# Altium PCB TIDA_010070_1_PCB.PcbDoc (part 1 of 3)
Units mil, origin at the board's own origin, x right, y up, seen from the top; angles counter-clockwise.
Board outline 3224 x 3643 mil, 4 copper layers (Top Layer, Ground, Power, Bottom Layer), stack 90.4 mil thick; 156 components, 57 nets, 333 pads, 411 vias.
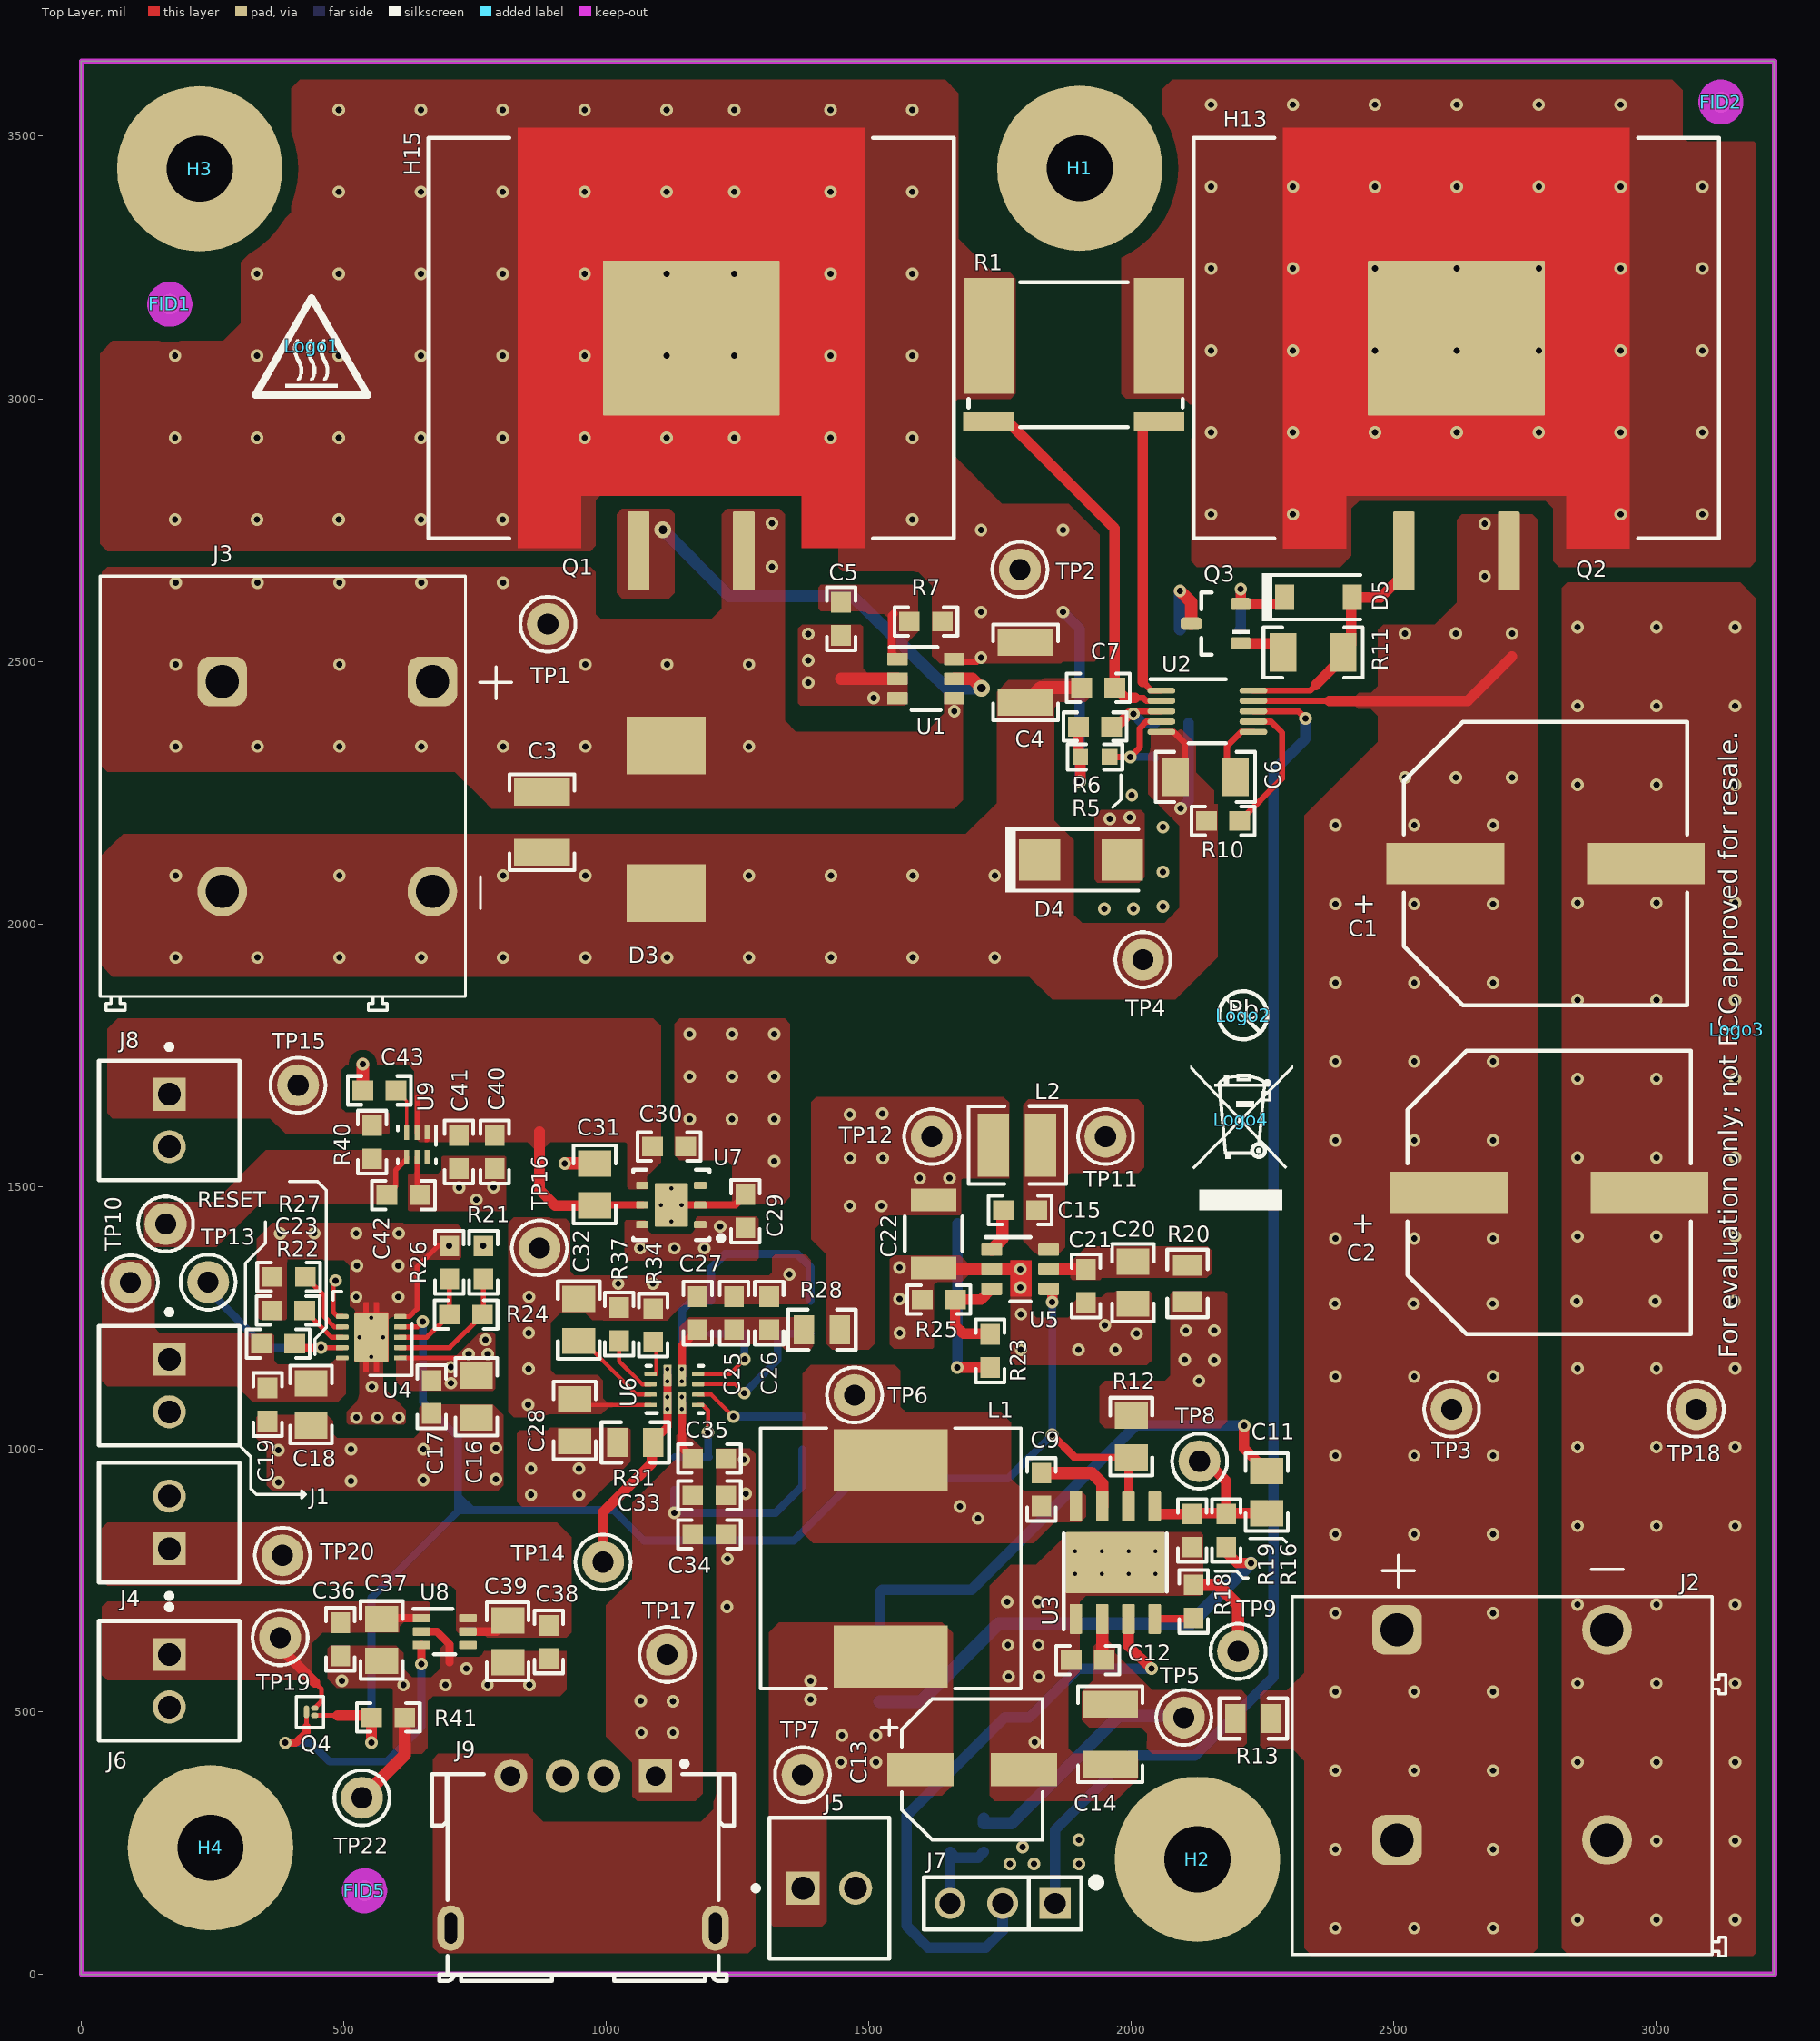
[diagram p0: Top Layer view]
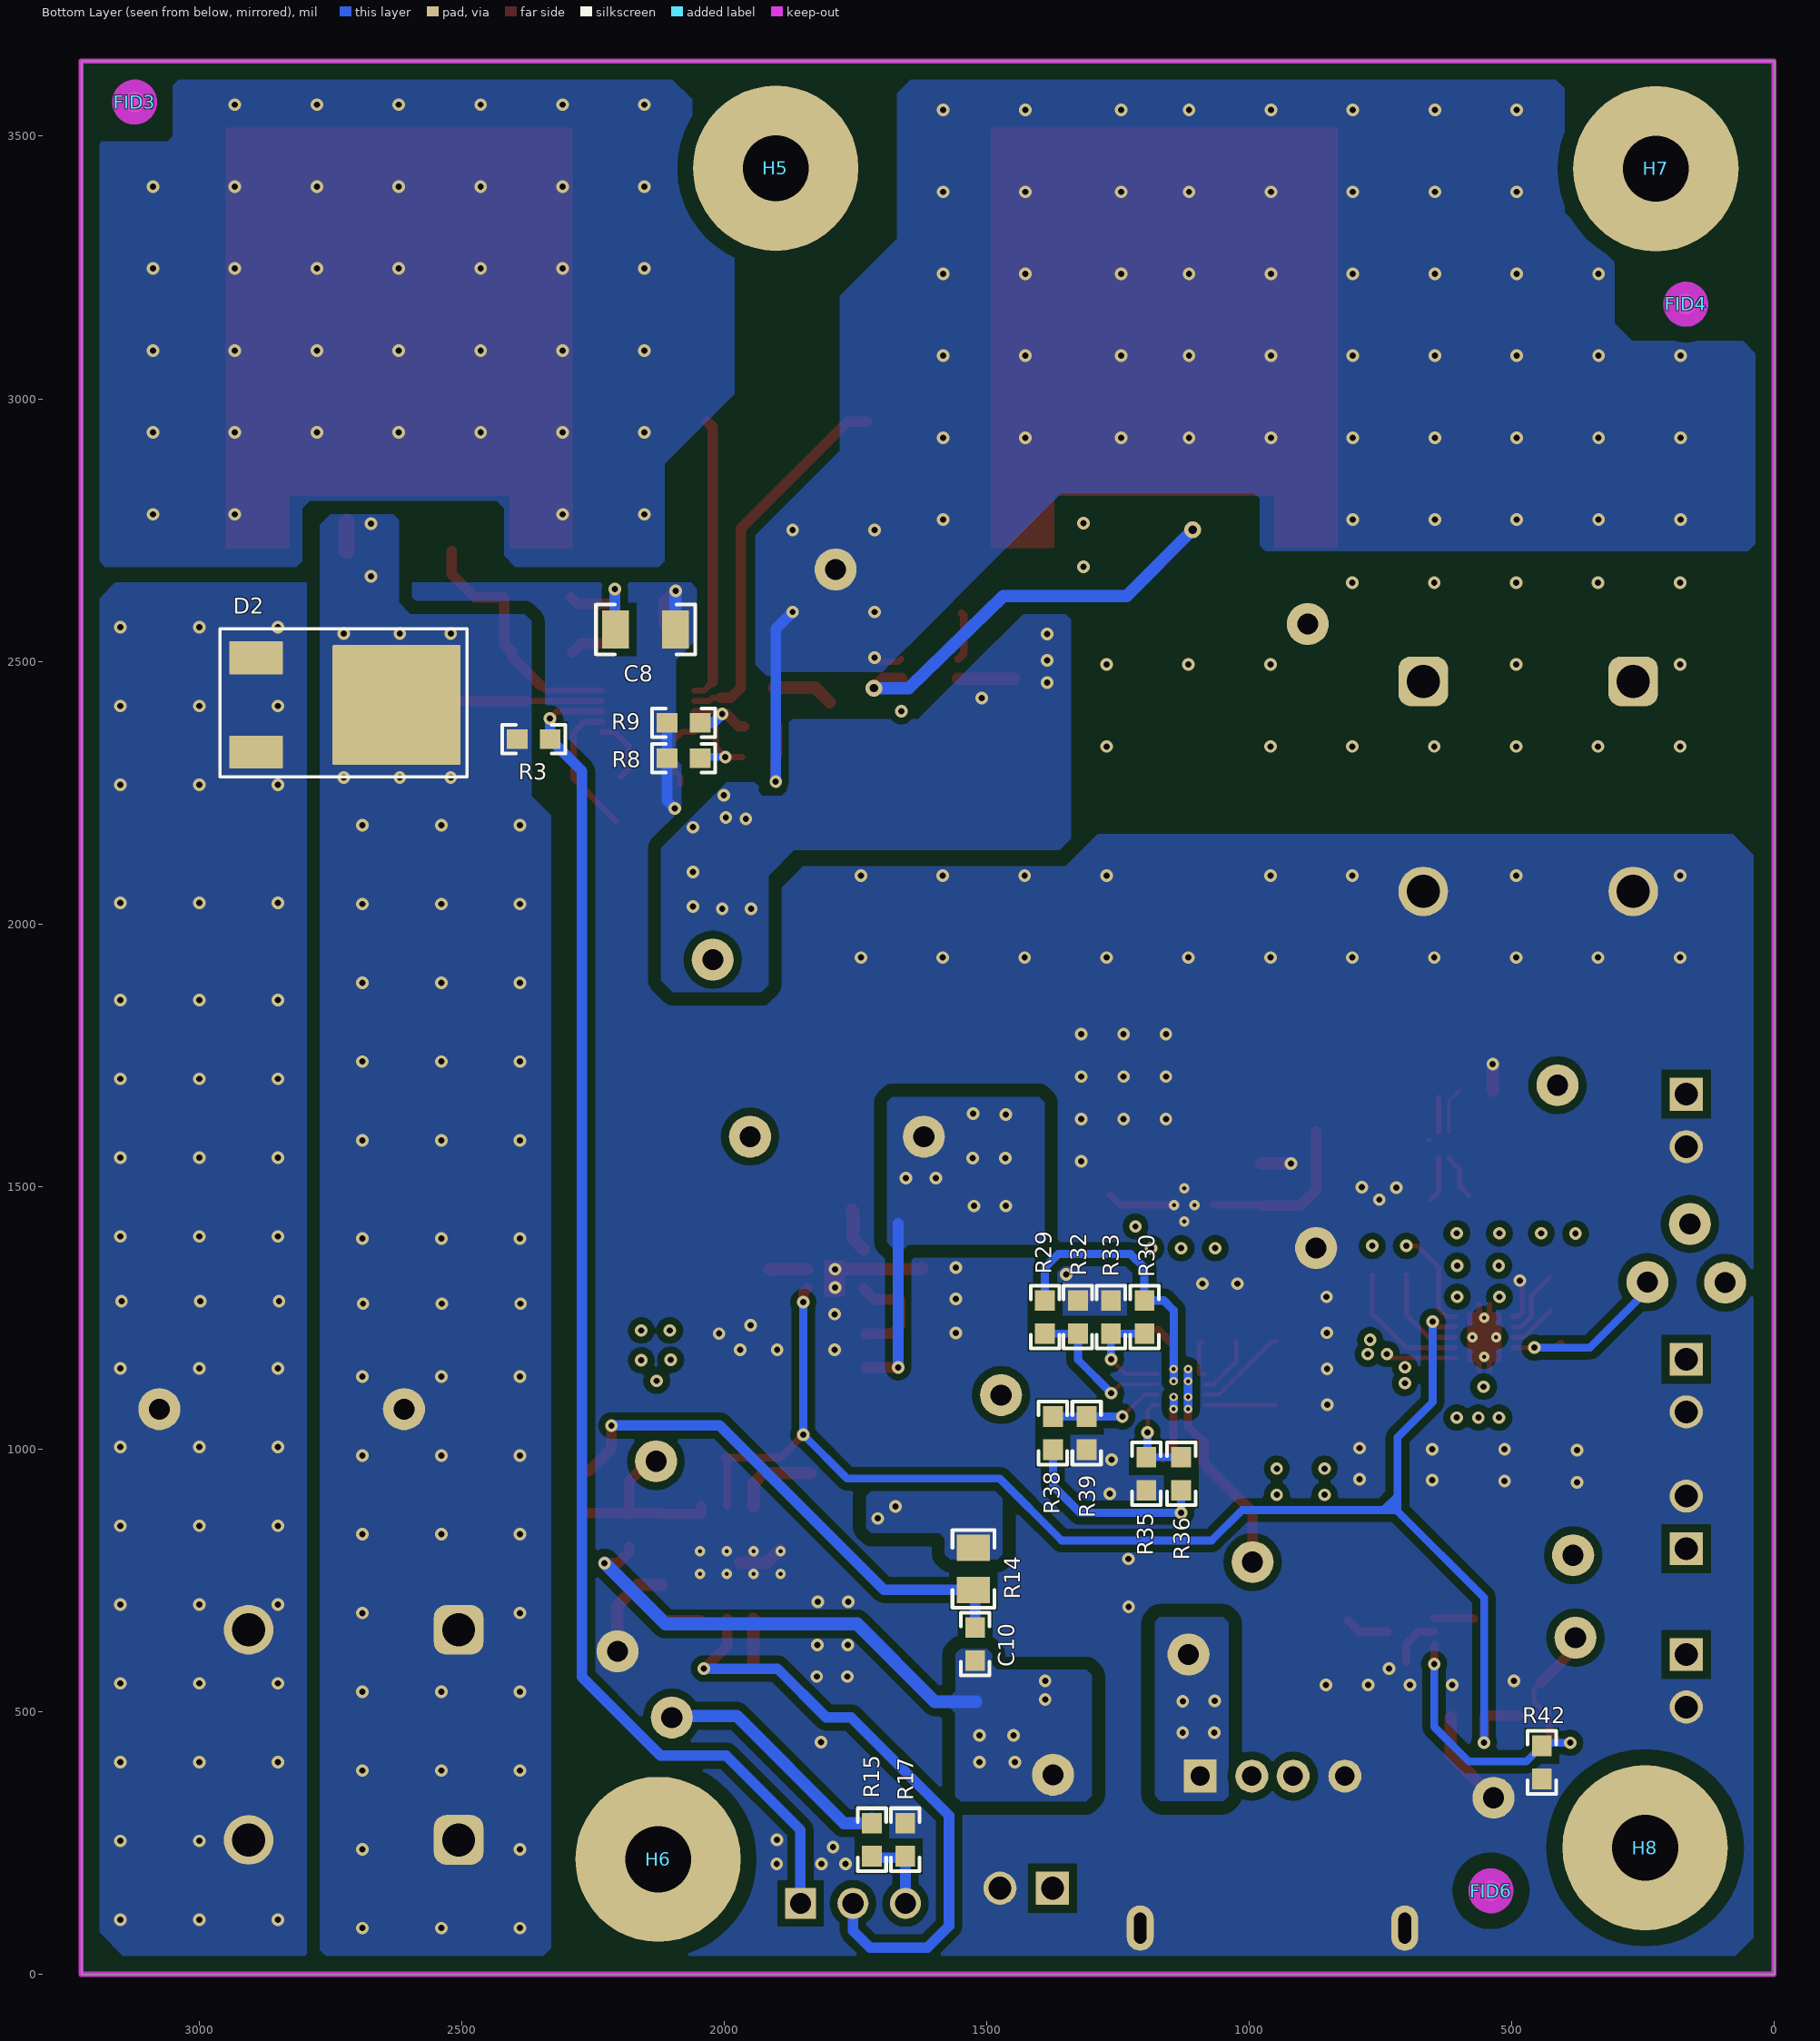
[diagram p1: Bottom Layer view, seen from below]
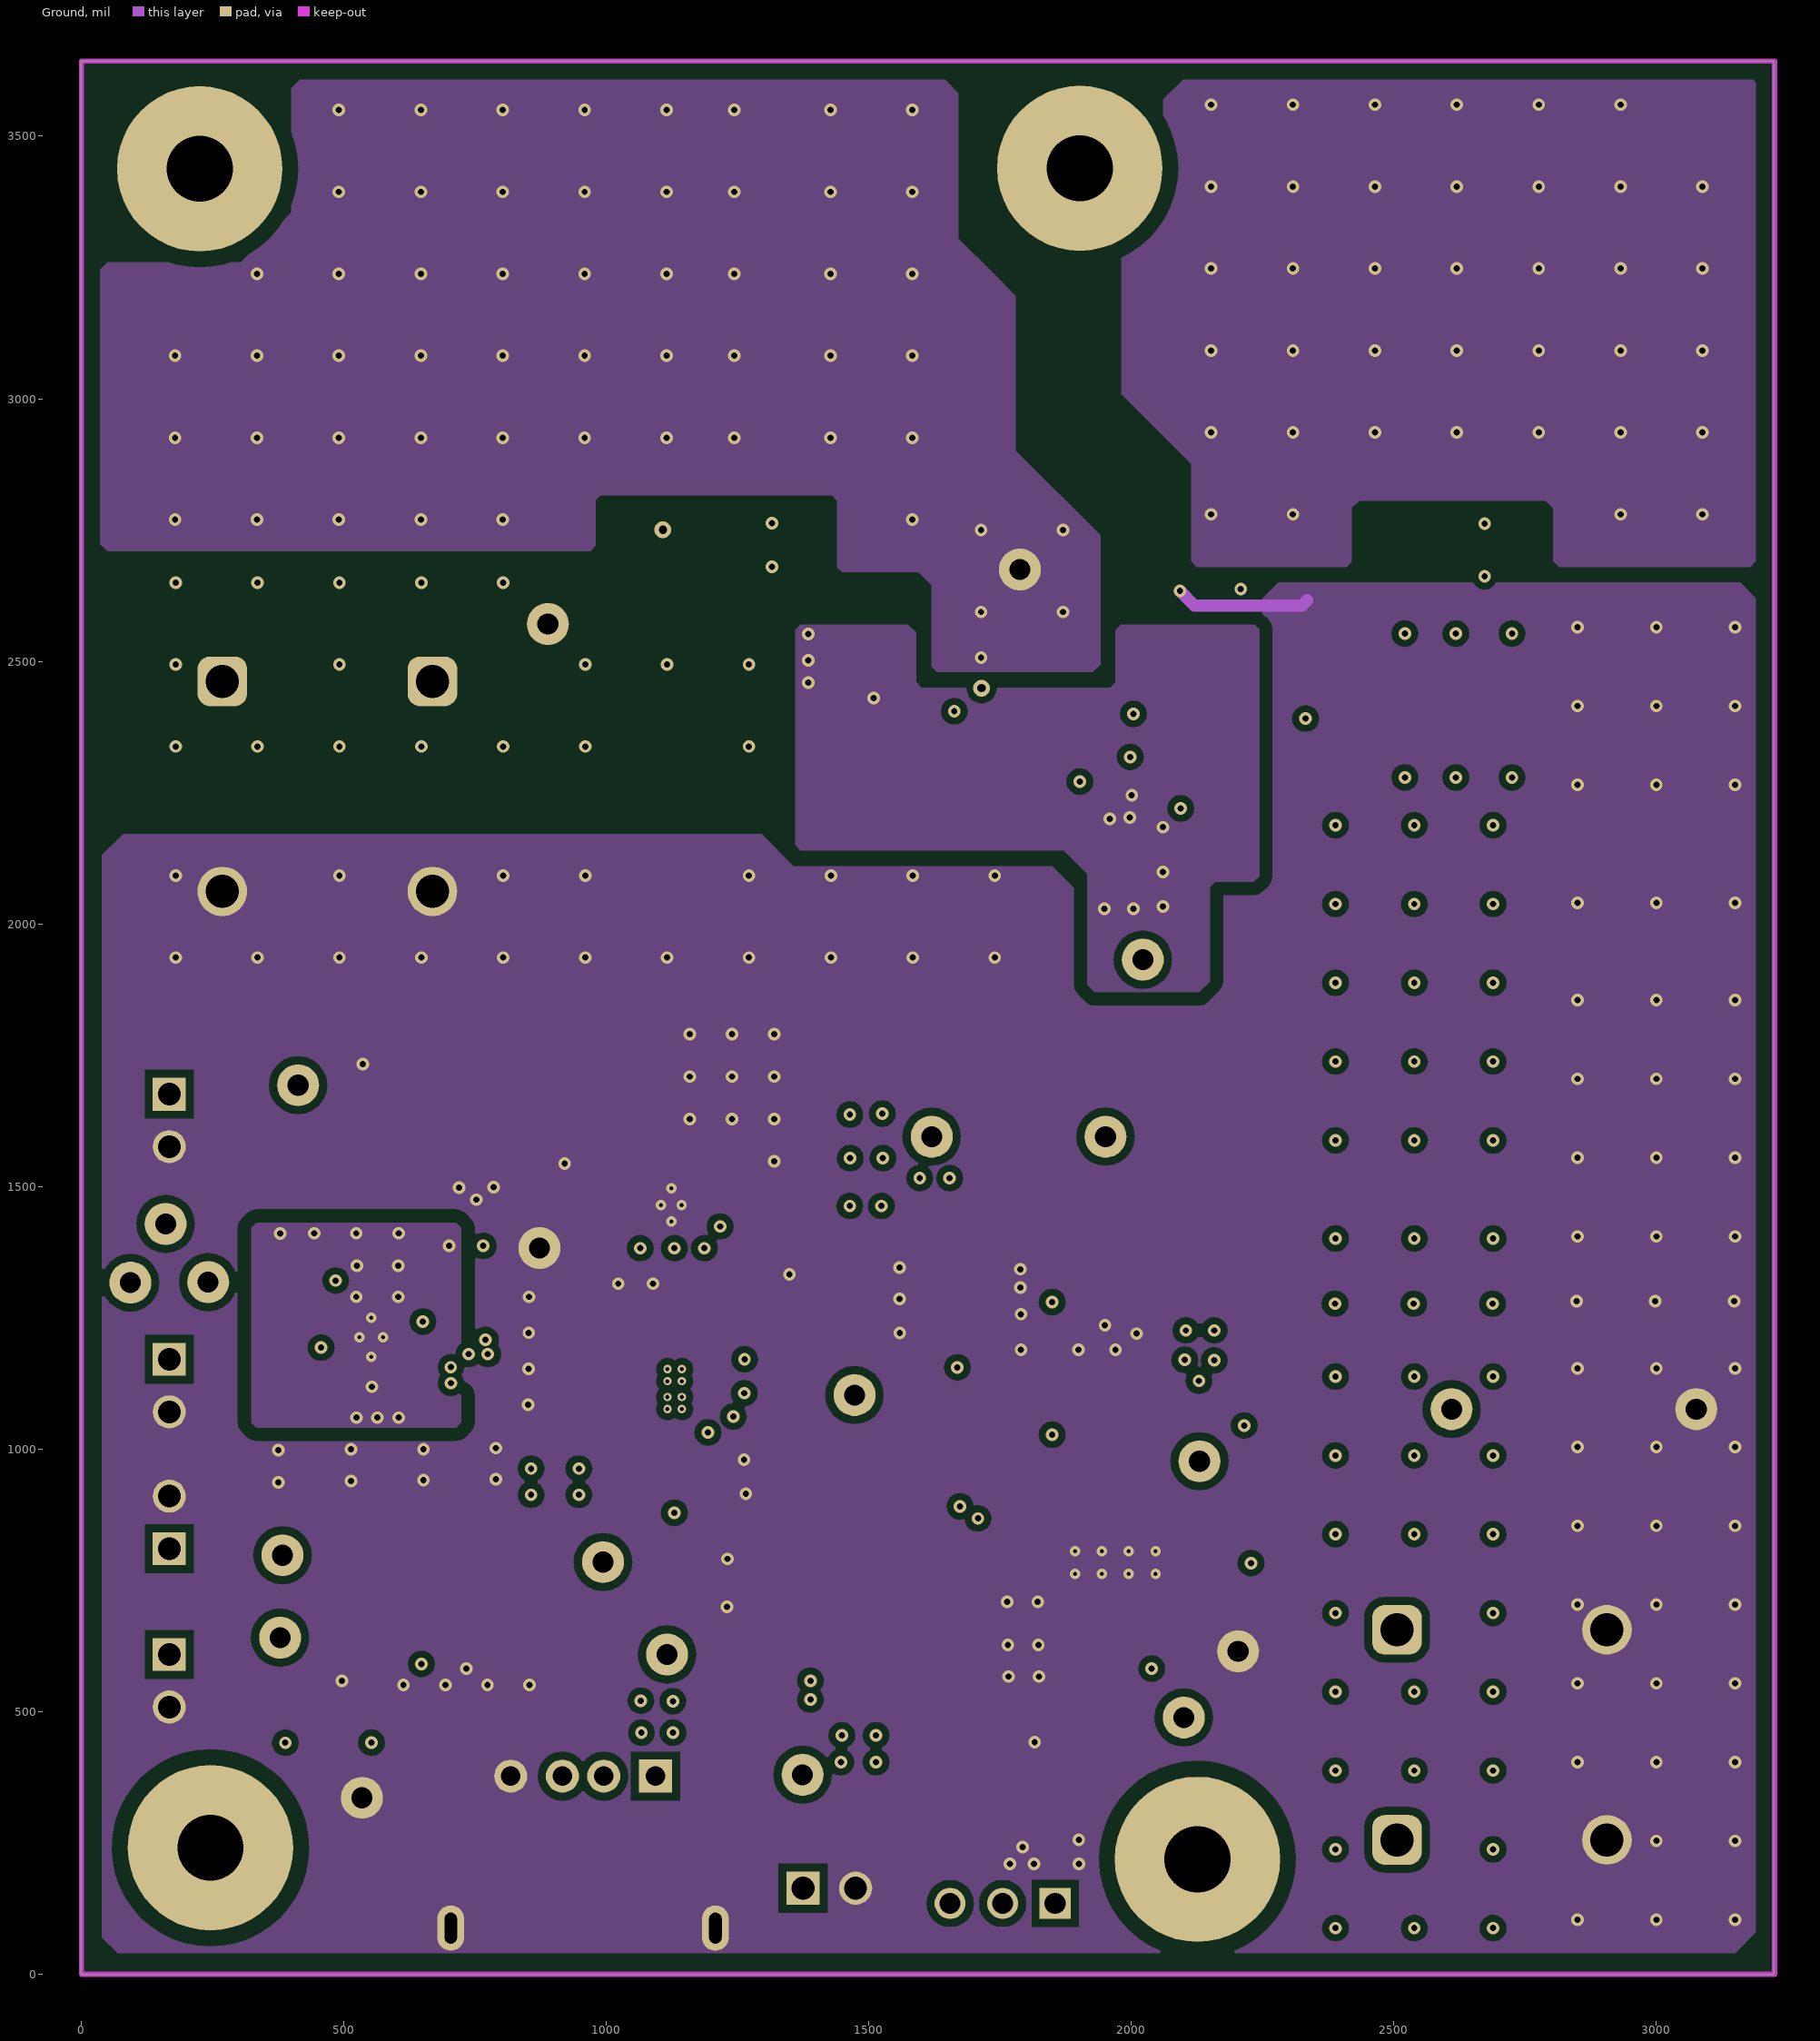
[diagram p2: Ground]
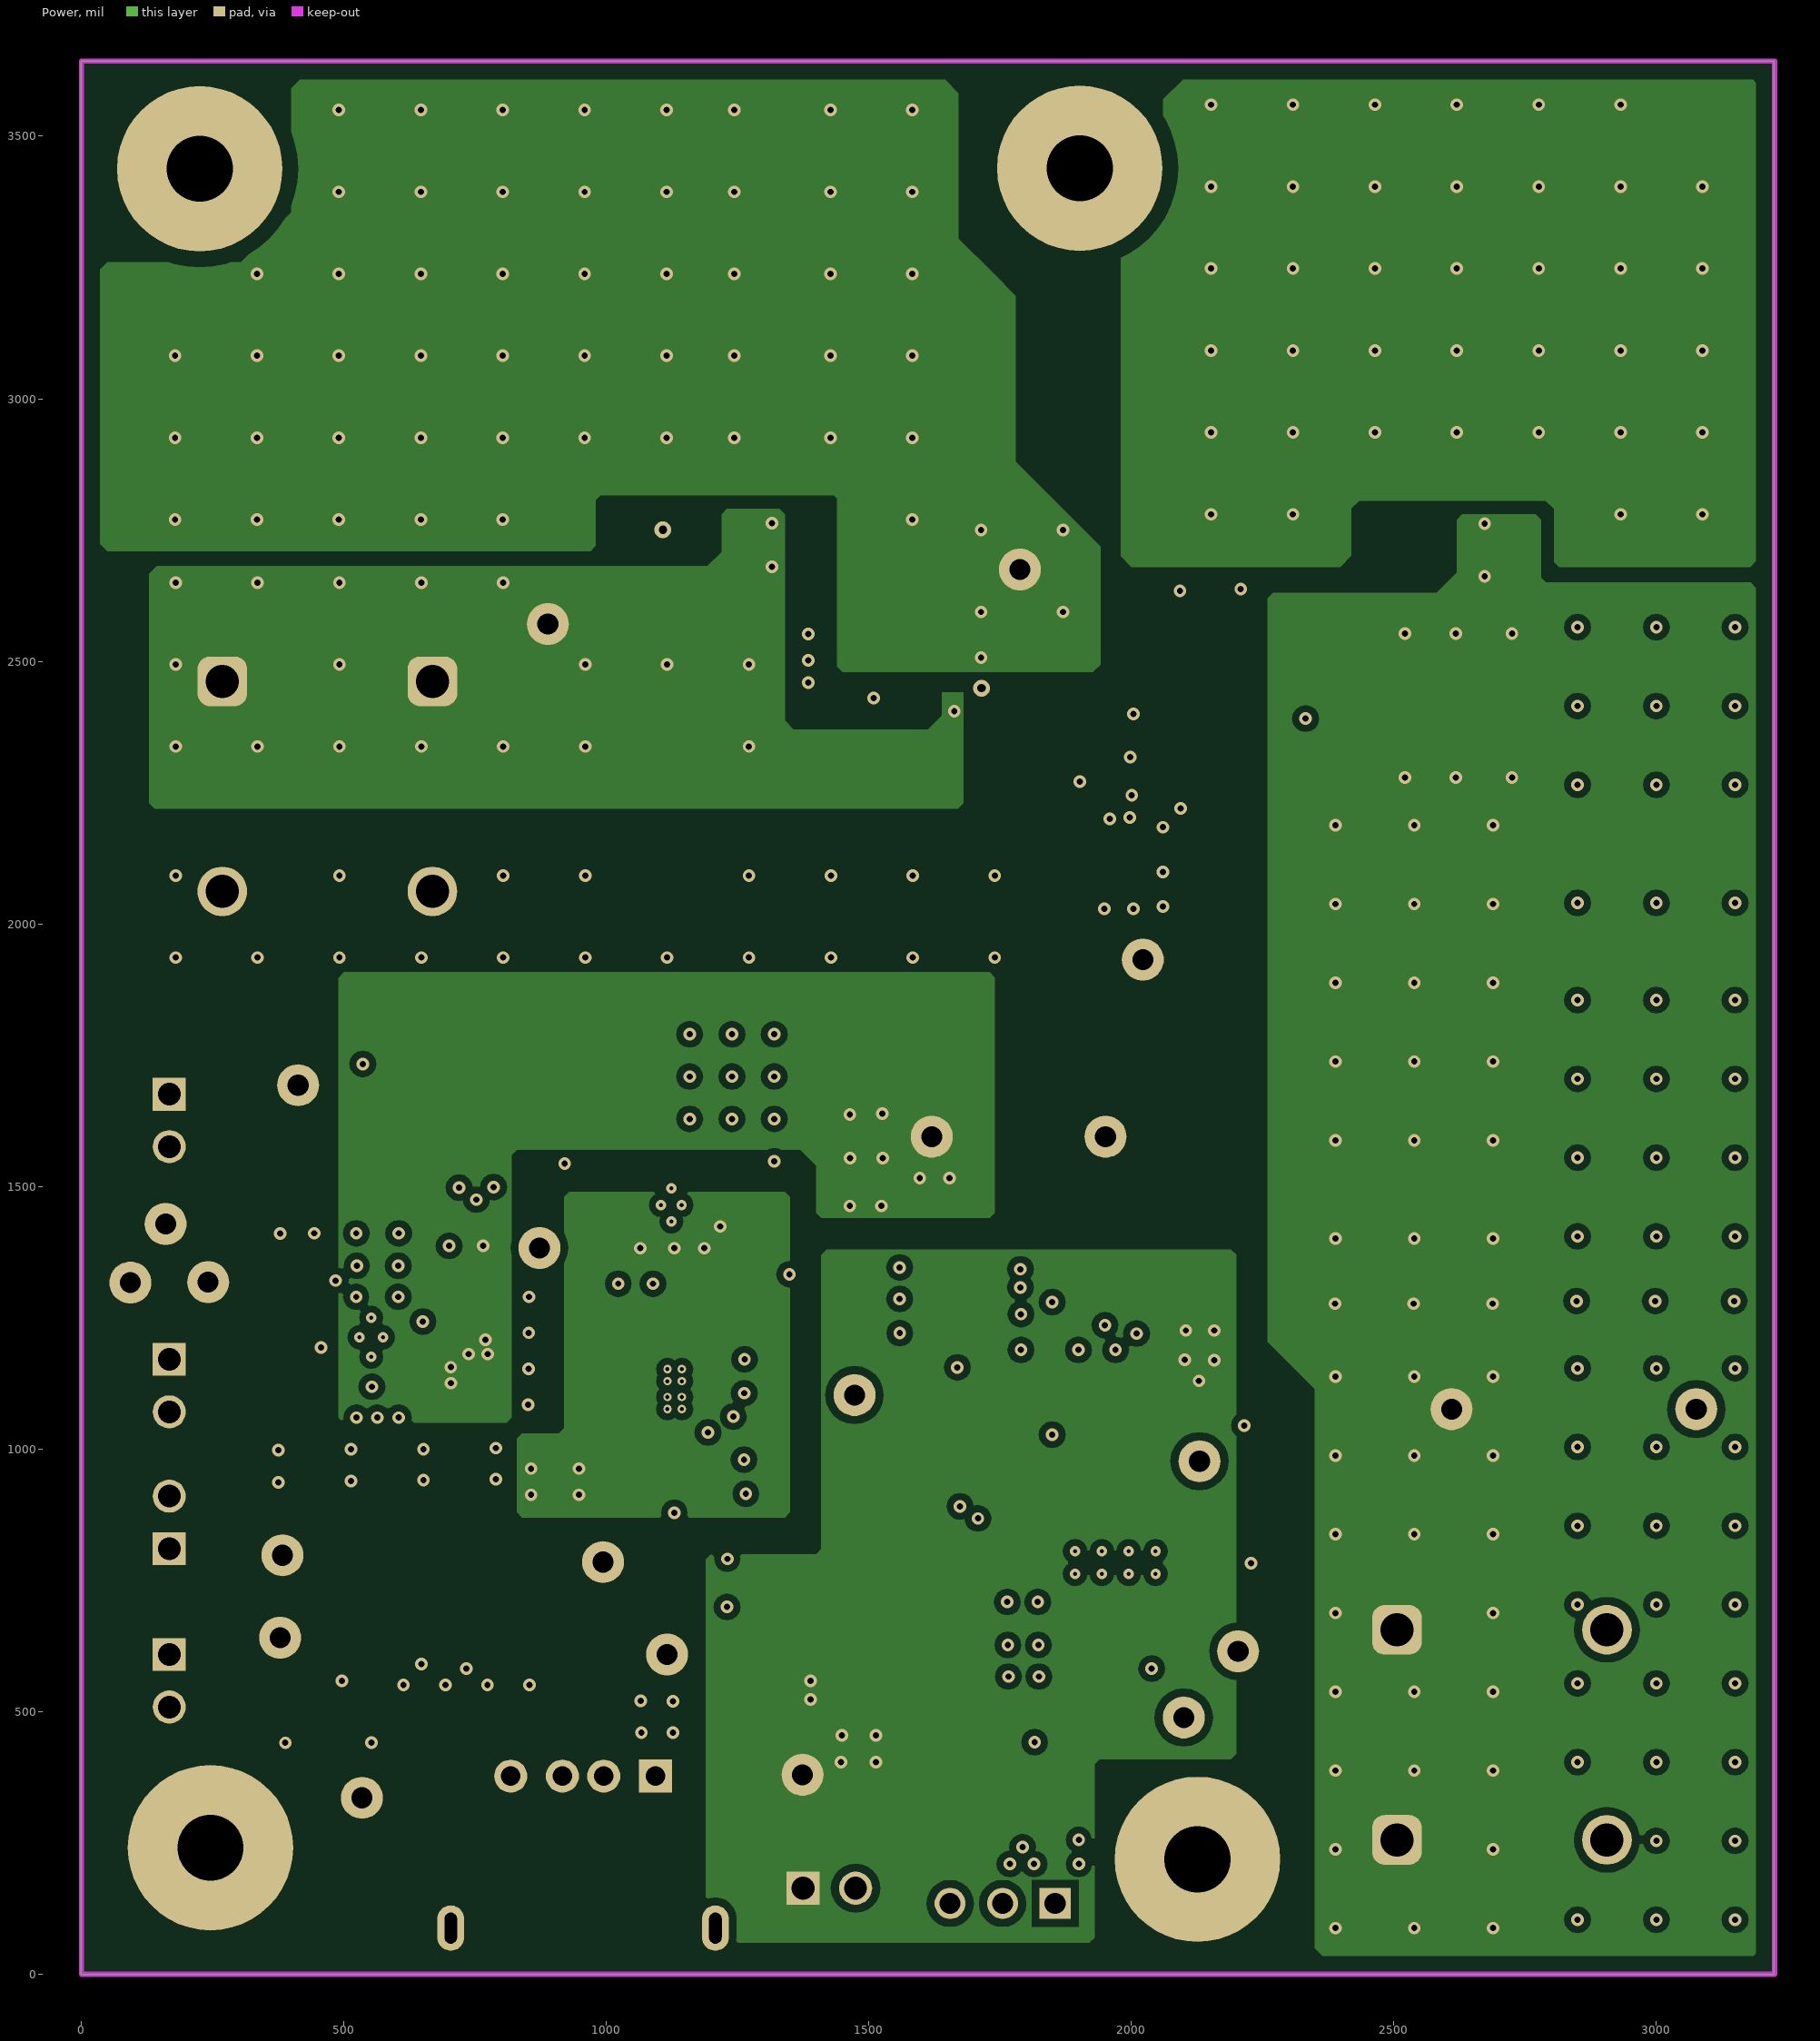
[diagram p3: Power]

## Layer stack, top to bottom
Top Solder: solder mask 0.4, Solder Resist, Dk 3.5
Top Layer: signal copper 2.8
Dielectric1: core 59.2, FR-4, Dk 4.8
Ground: signal copper 2.8
Dielectric 2: dielectric 10, Dk 4.2
Power: signal copper 2.8
Dielectric 3: dielectric 10, Dk 4.2
Bottom Layer: signal copper 2.8
Bottom Solder: solder mask 0.4, Solder Resist, Dk 3.5

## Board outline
0,0 3224,0 3224,3643 0,3643

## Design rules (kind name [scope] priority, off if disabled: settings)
AcuteAngle [All] p1: minimum=4.50000000000000E+0001 checktracksonly=FALSE
AssemblyTestPointUsage [All] p1: valid=2
BoardOutlineClearance BoardOutlineClearance_MountingHoles [OnCopper and InComponentClass('Mounting Holes')] p1: gap=39.37 ignorepadtopadclearanceinfootprint=FALSE
BoardOutlineClearance BoardOutlineClearance_Poly [OnCopper and IsPoly] p2: gap=25 ignorepadtopadclearanceinfootprint=FALSE
BoardOutlineClearance [OnCopper and Not InComponentClass('Logo') and not InComponentClass('FiducialMark') and not InRegion(1000,500,4000,800) and not InPoly] p3: gap=40 ignorepadtopadclearanceinfootprint=FALSE
Clearance room [WithinRoom('room Q4')] p1: gap=2 ignorepadtopadclearanceinfootprint=TRUE except(0: Arc-SMDPad Arc-Hole Track-Hole SMDPad-Hole THPad-Hole Via-Hole Fill-Hole Poly-Hole Region-Hole Text-Hole)
Clearance "MH PAD" [InPadClass('MH pad')] p2: gap=30 ignorepadtopadclearanceinfootprint=TRUE except(0: Arc-SMDPad Arc-THPad Arc-Hole Track-Hole SMDPad-Hole THPad-Hole Via-Hole Fill-Hole Poly-Hole Region-Hole Text-Hole)
Clearance Clearance_Keepouts [IsKeepOut] p3: gap=30 ignorepadtopadclearanceinfootprint=FALSE except(0: Arc-SMDPad Arc-THPad Arc-Hole Track-Hole SMDPad-Hole THPad-Hole Via-Hole Fill-Hole Poly-Hole Region-Hole Text-Hole)
Clearance Clearance_Poly [InPolygon] p4: gap=15 ignorepadtopadclearanceinfootprint=TRUE except(0: Arc-SMDPad Arc-Hole Track-Hole SMDPad-Hole THPad-Hole Via-Hole Fill-Hole Poly-Hole Region-Hole Text-Hole; 13: Via-Poly; 25: Poly-Poly)
Clearance [All] p5: gap=8 ignorepadtopadclearanceinfootprint=TRUE except(0: Arc-SMDPad Arc-THPad Arc-Hole Track-Hole SMDPad-Hole THPad-Hole Via-Hole Fill-Hole Poly-Hole Region-Hole Text-Hole; 7.8: Track-Track Track-SMDPad SMDPad-SMDPad SMDPad-THPad SMDPad-Via SMDPad-Fill SMDPad-Poly SMDPad-Region SMDPad-Text)
ComponentClearance "HEAT SINK" [InComponentClass('heat sink') vs InComponentClass('heat sink')] p1: gap=0 collisioncheckmode=3 verticalgap=0 showdistances=FALSE
ComponentClearance ComponentClearance_MountingHoles_FiducialMarks [InComponentClass('Mounting Holes') vs InComponentClass('FiducialMark')] p2: gap=50 collisioncheckmode=3 verticalgap=10 showdistances=FALSE
ComponentClearance ComponentClearance_Shunt [InComponentClass('Header') vs InComponentClass('Shunt')] p3: gap=0 collisioncheckmode=3 verticalgap=0 showdistances=FALSE
ComponentClearance ComponentClearance_Logo [InComponentClass('Logo')] p4: gap=50 collisioncheckmode=3 verticalgap=10 showdistances=FALSE
ComponentClearance ComponentClearance_ScrewToNut [(HasFootprint('NY PMS 440 0025 PH')) vs (HasFootprint('Keystone_1902C'))] p5: gap=5 collisioncheckmode=3 verticalgap=10 showdistances=FALSE
ComponentClearance ComponentClearance_MountingHoles [InComponentClass('Mounting Holes')] p6: gap=50 collisioncheckmode=3 verticalgap=100000 showdistances=FALSE
ComponentClearance ComponentClearance_SmallPassives [HasFootprint('0201*') or HasFootprint('0402*') or HasFootprint('0508') or HasFootprint('0603*') or HasFootprint('0612') or HasFootprint('0805*') or HasFootprint('0815*') or HasFootprint('0830*') or HasFootprint('1206*') or HasFootprint('1210*') or HasFootprint('1808*') or HasFootprint('1812*') or HasFootprint('1825*') or HasFootprint('2010*') or HasFootprint('2220*') or HasFootprint('2225*') or HasFootprint('2512*') or HasFootprint('2728*') or HasFootprint('3518*') vs HasFootprint('0201*') or HasFootprint('0402*') or HasFootprint('0508') or HasFootprint('0603*') or HasFootprint('0612') or HasFootprint('0805*') or HasFootprint('0815*') or HasFootprint('0830*') or HasFootprint('1206*') or HasFootprint('1210*') or HasFootprint('1808*') or HasFootprint('1812*') or HasFootprint('1825*') or HasFootprint('2010*') or HasFootprint('2220*') or HasFootprint('2225*') or HasFootprint('2512*') or HasFootprint('2728*') or HasFootprint('3518*')] p7: gap=14.96 collisioncheckmode=3 verticalgap=10 showdistances=FALSE
ComponentClearance ComponentClearance_THtoSMT [IsThruComponent vs IsSMTComponent] p8: gap=15 collisioncheckmode=3 verticalgap=30 showdistances=FALSE
ComponentClearance ComponentClearance_THtoTH [IsThruComponent vs IsThruComponent] p9: gap=30 collisioncheckmode=3 verticalgap=30 showdistances=FALSE
ComponentClearance [All] p10: gap=23 collisioncheckmode=3 verticalgap=10 showdistances=FALSE
DiffPairsRouting [All] p1: maxlimit=100 minlimit=10 mostfreqgap=10 toplayer_minwidth=15 toplayer_maxwidth=15 toplayer_prefwidth=15 midlayer1_minwidth=15 midlayer1_maxwidth=15 midlayer1_prefwidth=15 midlayer2_minwidth=15 midlayer2_maxwidth=15 midlayer2_prefwidth=15 bottomlayer_minwidth=15 bottomlayer_maxwidth=15 bottomlayer_prefwidth=15 maxuncoupledlength=1000
FabricationTestPointUsage TestPointUsage [All] p1: valid=2 allowmultiple=FALSE
FabricationTestpoint Testpoint [All] p1: side=3 testpointundercomponent=TRUE minsize=40 maxsize=100 preferedsize=60 minholesize=0 maxholesize=40 preferedholesize=32 testpointgrid=1 allowsidetop=TRUE allowsidebottom=TRUE usegrid=TRUE gridtolerance=0.01
FanoutControl Fanout_LCC [IsLCC] p1: bgadir=Out bgaviamode=Centered fanoutstyle=Auto fanoutdirection=Alternating viagrid=1 // Fanout_LCC (Default Rule)
FanoutControl Fanout_BGA [IsBGA] p2: bgadir=Out bgaviamode=Centered fanoutstyle=Auto fanoutdirection=Alternating viagrid=1 // Fanout_BGA (Default Rule)
FanoutControl Fanout_Default [All] p4: bgadir=Out bgaviamode=Centered fanoutstyle=Auto fanoutdirection=Alternating viagrid=1 // Fanout_Default (Default Rule)
FanoutControl Fanout_Small [(CompPinCount < 5)] p5: bgadir=Out bgaviamode=Centered fanoutstyle=Auto fanoutdirection=OutThenIn viagrid=1 // Fanout_Small (Default Rule)
HoleSize [All] p1: absolutevalues=TRUE maxlimit=251 minlimit=7.87 maxpercent=80.000 minpercent=20.000
MinimumAnnularRing MinimumAnnularRing_ThermalPadVias [IsVia and InAnyComponent] p1: minimumring=5.91
MinimumAnnularRing [All] p2: minimumring=4
MinimumSolderMaskSliver MinimumSolderMaskSliver_Logo [InComponentClass('Logo') vs InComponentClass('Logo')] p1: minsoldermaskwidth=0.7
MinimumSolderMaskSliver [All] p2: minsoldermaskwidth=3.94
PlaneConnect [All] p1: planeconnectstyle=Direct reliefexpansion=10 reliefentries=4 reliefconductorwidth=10 reliefairgap=10
PolygonConnect [All] p1: connectstyle=Direct reliefconductorwidth=10 reliefentries=4 polygonreliefangle="90 Angle" airgapwidth=10
RoomDefinition "room Q4" [All] p1: confinementstyle=ConfineOut formatcopy=TRUE lockcomponents=FALSE outline 420,520 480,520 480,470 420,470
RoutingVias ThermalPadVias [IsVia and InAnyComponent] p1: holewidth=7.87 width=19.68 viastyle="Through Hole" minholewidth=7.87 minwidth=19.68 maxholewidth=12.99 maxwidth=23.62
RoutingVias [All] p2: holewidth=12 width=24 viastyle="Through Hole" minholewidth=7 minwidth=16 maxholewidth=40 maxwidth=65
SilkToBoardRegionClearance [Not ((IsComment or IsDesignator) And (Hide <> 'False')) and not InRegion(1000,500,4000,800)] p1:
SilkToSilkClearance SilkToSilkClearance_Pb-FreeLogo [(HasFootprint('Pb-Free_Overlay_Medium') OR HasFootprint('Pb-Free_Overlay_Small')) vs (HasFootprint('Pb-Free_Overlay_Medium') OR HasFootprint('Pb-Free_Overlay_Small'))] p1: silktosilkclearance=0
SilkToSilkClearance [All] p2: silktosilkclearance=3.94
SilkToSolderMaskClearance SilkToComponentPadClearance [(IsPad or IsFill or IsRegion) and InAnycomponent] p1: minsilkscreentomaskgap=5 clearancetoexposedcopper=TRUE
SilkToSolderMaskClearance "Silk to Solder Mask Opening" [All] p2: minsilkscreentomaskgap=3.94 clearancetoexposedcopper=FALSE
SolderMaskExpansion [All] p1: expansion=1.97
UnRoutedNet [All] p1: checkbadconnections=TRUE
Width [All] p1: maxlimit=100 minlimit=6 preferedwidth=10 checkconnectedcopper=TRUE
14 further rules are at their usual default settings.

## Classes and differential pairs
component class TIDA_010070_Sheet2_09: C15 C16 C17 C18 C19 C20 C21 C22 C23 C25 C26 C27 C28 C29 C30 C31 C32 C33 C34 C35 C36 C37 C38 C39 C40 C41 C42 C43 L2 Q4 R20 R21 R22 R23 R24 R25 R26 R27 R28 R29 R30 R31 R32 R33 R34 R35 R36 R37 R38 R39 R40 R41 R42 RESET TP10 TP11 TP12 TP13 TP14 TP15 TP16 TP17 TP18 TP19 TP20 TP21 TP22 U4 U5 U6 U7 U8 U9
component class Header: J7
pad class "MH pad": H1-1 H2-1 H3-1 H4-1 H5-0 H6-0 H7-0 H8-0
component class TIDA_010070_Sheet1_09: C1 C2 C3 C4 C5 C6 C7 C8 C9 C10 C11 C12 C13 C14 D2 D3 D4 D5 H13 H15 J1 J2 J3 J4 J5 J6 J7 J8 J9 L1 Q1 Q2 Q3 R1 R3 R5 R6 R7 R8 R9 R10 R11 R12 R13 R14 R15 R16 R17 R18 R19 TP1 TP2 TP3 TP4 TP5 TP6 TP7 TP8 TP9 U1 U2 U3
component class AssemblyNote: ZZ1 ZZ2 ZZ3 ZZ4
component class FiducialMark: FID1 FID2 FID3 FID4 FID5 FID6
component class TIDA_010070_Hardware: FID1 FID2 FID3 FID4 FID5 FID6 H1 H2 H3 H4 H5 H6 H7 H8 Logo1 Logo2 Logo3 Logo4 ZZ1 ZZ2 ZZ3 ZZ4
component class "Mounting Holes": H1 H2 H3 H4
component class "heat sink": H13 H15 Q1 Q2

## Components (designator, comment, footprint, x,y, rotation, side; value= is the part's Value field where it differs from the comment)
C1 "EEV-EB2C330SQ" EB_H16 2789,2115 r0 top locked value=33uF
C2 "EEV-EB2C330SQ" EB_H16 2796,1489 r0 top locked value=33uF
C3 "CGA6N3X7R2A225K230AB" 1210_250 878,2194 r90 top value=2.2uF
C4 "CGA6N3X7R2A225K230AB" 1210_250 1799,2479 r90 top value=2.2uF
C5 "HMK107B7104KAHT" 0603 1447.23,2581 r270 top value=0.1uF
C6 "CC1206KRX7R9BB123" 1206 2141,2280.09 r0 top value=0.012uF
C7 "HMK107B7104KAHT" 0603 1937,2450 r180 top value=0.1uF
C8 "12065C103KAT2A" 1206 2149.86,2561 r0 bottom value=0.01uF
C9 "C0603C222K5RACTU" 0603 1829,923 r90 top value=2200pF
C10 "C0603C222K5RACTU" 0603 1522,628.84 r90 bottom value=2200pF
C11 "C0805C470J5GACTU" 0805_HV 2258,918.1 r90 top value=47pF
C12 "HMK107B7104KAHT" 0603 1917,597.8 r180 top value=0.1uF
C13 "EEE-FK1V470P" SM_RADIAL_D 1697,390 r0 top value=47uF
C14 "CGA6N3X7R2A225K230AB" 1210_250 1960,457 r90 top value=2.2uF
C15 "06033C104KAT2A" 0603 1788.46,1454.85 r0 top value=0.1uF
C16 "C2012X8R1C105K125AB" 0805_HV 752.64,1100 r90 top value=1uF
C17 "06033C104KAT2A" 0603 667.64,1099.5 r270 top value=0.1uF
C18 "GRM21BZ71E106KE15L" 0805_HV 438,1085.03 r90 top value=10uF
C19 "06033C104KAT2A" 0603 355,1085 r270 top value=0.1uF
C20 "C2012X7R1V475K125AC" 0805_HV 2003.19,1317 r90 top value=4.7uF
C21 "06033C104KAT2A" 0603 1913.46,1310.79 r90 top value=0.1uF
C22 "C3225X5R1C156M250AA" 1210_280 1623.46,1409.85 r90 top value=15uF
C23 "C0603C223K4RACTU" 0603 394.5,1264 r180 top value=0.022uF
C25 "06033C104KAT2A" 0603 1243.5,1259 r270 top value=0.1uF
C26 "06033C104KAT2A" 0603 1310.5,1259 r270 top value=0.1uF
C27 "06033C104KAT2A" 0603 1174.5,1259 r270 top value=0.1uF
C28 "C2012X7R1V475K125AC" 0805_HV 940,1055 r270 top value=4.7uF
C29 "06033C104KAT2A" 0603 1265,1452.91 r90 top value=0.1uF
C30 "06033C104KAT2A" 0603 1119.89,1576 r0 top value=0.1uF
C31 "C2012X8R1C105K125AB" 0805_HV 978,1504 r270 top value=1uF
C32 "C0805C105K5RACTU" 0805_HV 948,1246 r270 top value=1uF
C33 "06033C104KAT2A" 0603 1196.5,912 r180 top value=0.1uF
C34 "06033C104KAT2A" 0603 1196.5,837.45 r180 top value=0.1uF
C35 "06033C104KAT2A" 0603 1196.5,982 r180 top value=0.1uF
C36 "06033C104KAT2A" 0603 494,638 r270 top value=0.1uF
C37 "C2012X8R1C105K125AB" 0805_HV 572.33,636.58 r90 top value=1uF
C38 "06033C104KAT2A" 0603 891,633 r270 top value=0.1uF
C39 "C2012X8R1C105K125AB" 0805_HV 812.54,634 r90 top value=1uF
C40 "06033C104KAT2A" 0603 788,1565.8 r270 top value=0.1uF
C41 "GCM188R71C105KA64D" 0603 719.16,1565.8 r270 top value=1uF
C42 "06033C104KAT2A" 0603 614,1483.93 r0 top value=0.1uF
C43 "C0603C332K5RACTU" 0603 568,1683 r180 top value=3300pF
D2 "VS-6CWQ10FN-M3" DPAK 2758,2417 r180 bottom value=100V
D3 "5.0SMDJ75CA" SMC_Bi 1114.33,2199 r90 top value=75V
D4 "10MQ100NTRPBF" SMA 1903.93,2122 r0 top value=100V
D5 "1N4148W-7-F" SOD-123 2356.47,2622 r0 top value=100V
FID1 "Fiducial" Fiducial10-20 169,3180 r0 top
FID2 "Fiducial" Fiducial10-20 3123,3565 r0 top
FID3 "Fiducial" Fiducial10-20 3123,3565 r180 bottom
FID4 "Fiducial" Fiducial10-20 169,3180 r90 bottom
FID5 "Fiducial" Fiducial10-20 540,159 r90 top
FID6 "Fiducial" Fiducial10-20 540,159 r90 bottom
H1 "NY PMS 440 0025 PH" "NY PMS 440 0025 PH" 1902,3439 r0 top locked
H2 "NY PMS 440 0025 PH" "NY PMS 440 0025 PH" 2126,219 r0 top locked
H3 "NY PMS 440 0025 PH" "NY PMS 440 0025 PH" 226,3438 r0 top locked
H4 "NY PMS 440 0025 PH" "NY PMS 440 0025 PH" 246.37,241 r0 top locked
H5 "1902C" Keystone_1902C 1902.53,3439 r180 bottom locked
H6 "1902C" Keystone_1902C 2126,219 r180 bottom locked
H7 "1902C" Keystone_1902C 226,3438 r180 bottom locked
H8 "1902C" Keystone_1902C 246.37,241 r180 bottom locked
H13 "7109DG" Aavid_7109DG 2619,3115.49 r0 top locked
H15 "7109DG" Aavid_7109DG 1162,3115.62 r0 top
J1 "282834-2" TEC_282834-2 168,1121 r270 top
J2 "1986660-2" TE-1986660-2 2706,456 r0 top locked
J3 "1986660-2" TE-1986660-2 469,2262 r270 top locked
J4 "282834-2" TEC_282834-2 168,860.44 r90 top
J5 "282834-2" TEC_282834-2 1425,164 r0 top
J6 "282834-2" TEC_282834-2 168,559 r270 top
J7 "PEC03SAAN" CONN_PEC03SAAN 1755,135 r180 top locked
J8 "282834-2" TEC_282834-2 168,1626 r270 top
J9 "614 104 150 121" WURTH_614104150121 956.03,377.37 r0 top
L1 "MSS1210-154KE" MSS1210 1542,792 r270 top locked value=150uH
L2 "ME3220-682MLB" ME3220 1782.19,1579 r180 top locked value=6.8uH
Logo1 "CAUTION HOT SURFACE" IEC_HotSurface_Small 439,3100 r0 top (schematic designator LOGO1)
Logo2 "Pb-Free Symbol" Pb-Free_Overlay_Small 2213,1826 r0 top
Logo3 "FCC disclaimer" FCC_disclaimer 3153,1799 r90 top
Logo4 "WEEE logo" WEEE_Minimum 2208.52,1627 r0 top
Q1 "CSD19536KTT" KTT0002A 1162,2981.76 r90 top locked value=100V
Q2 "CSD19536KTT" KTT0002A 2619,2981.64 r90 top locked value=100V
Q3 "MMBT5401LT1G" SOT-23 2161.28,2572 r180 top value="150 V"
Q4 "CSD25501F3" YJN0003A 438.11,499.89 r180 top value=-20V
R1 "WSL40262L000FEB" WSL4026_310 1891,3084 r180 top locked value=0.002
R3 "CRCW0603102KFKEA" 0603 2363,2351.75 r180 bottom value=102k
R5 "CRCW060395K3FKEA" 0603_HV 1930.93,2318 r180 top value=95.3k
R6 "RT0603BRD0795K3L" 0603 1930.93,2375.75 r180 top value=95.3k
R7 "CRCW0603100RFKEA" 0603 1609,2576 r180 top value=100
R8 "CRCW06034K12FKEA" 0603 2077.52,2315.52 r0 bottom value=4.12k
R9 "RG1608P-7151-B-T5" 0603 2077.5,2383 r0 bottom value=7.15k
R10 "RG1608P-303-B-T5" 0603 2175,2196 r0 top value=30.0k
R11 "RC1206FR-071K02L" 1206 2346.38,2517 r180 top value=1.02k
R12 "CRCW080525K5FKEA" 0805_HV 2000,1024 r90 top value=25.5k
R13 "5106" 5106 2233,487 r180 top value=0
R14 "ERJ-6ENF4223V" 0805_HV 1525.53,772 r270 bottom value=422k
R15 "CRCW0603113KFKEA" 0603 1719,256.25 r270 bottom value=113k
R16 "RC0603FR-07576KL" 0603 2181,845 r90 top value=576k
R17 "CRCW060320K0FKEA" 0603 1655.32,256.25 r90 bottom value=20.0k
R18 "CRCW0603187KFKEA" 0603 2119,710 r90 top value=187k
R19 "RC0603FR-0749K9L" 0603 2116,845 r270 top value=49.9k
R20 "5106" 5106 2107.19,1315 r90 top value=0
R21 "CRCW060324K9FKEA" 0603 766,1355.5 r270 top value=24.9k
R22 "CRCW060349K9FKEA" 0603 375.21,1201 r0 top value=49.9k
R23 "CRCW060388K7FKEA" 0603 1731,1187 r90 top value=88.7k
R24 "CRCW06031K40FKEA" 0603 733,1256 r180 top value=1.40k
R25 "CRCW060322K1FKEA" 0603 1633.46,1284.85 r180 top value=22.1k
R26 "CRCW06038K06FKEA" 0603 701,1355.5 r90 top value=8.06k
R27 "CRCW060326K7FKEA" 0603 395.5,1328 r180 top value=26.7k
R28 "5106" 5106 1411.5,1227 r180 top value=0
R29 "CRCW060323K7FKEA" 0603 1389.5,1251.5 r270 bottom value=23.7k
R30 "CRCW060323K2FKEA" 0603 1200,1251.5 r270 bottom value=23.2k
R31 "5106" 5106 1055.8,1013 r180 top value=0
R32 "CRCW06034K99FKEA" 0603 1326.5,1251.5 r90 bottom value=4.99k
R33 "CRCW060313K3FKEA" 0603 1264,1251.5 r90 bottom value=13.3k
R34 "CRCW06030000Z0EA" 0603 1089.8,1236 r90 top value=0
R35 "CRCW06036K98FKEA" 0603 1196,953.05 r270 bottom value=6.98k
R36 "CRCW060314K3FKEA" 0603 1130,953.05 r270 bottom value=14.3k
R37 "CRCW060351K1FKEA" 0603 1025,1238 r90 top value=51.1k
R38 "CRCW060323K7FKEA" 0603 1374,1030.5 r90 bottom value=23.7k
R39 "CRCW06034K99FKEA" 0603 1310,1030.5 r270 bottom value=4.99k
R40 "CRCW060310K0FKEA" 0603 554.25,1584.5 r90 top value=10.0k
R41 "CRCW060312K7FKEA" 0603 585.12,489 r0 top value=12.7k
R42 "CRCW060310K2FKEA" 0603 442.82,403.71 r270 bottom value=10.2k
RESET "5000" Keystone5000 161,1428.75 r180 top
TP1 "5000" Keystone5000 889,2571 r0 top
TP2 "5000" Keystone5000 1788,2675 r90 top
TP3 "5000" Keystone5000 2610,1076.19 r90 top locked
TP4 "5001" Keystone5001 2022,1932 r90 top
TP5 "5000" Keystone5000 2100,489 r0 top
TP6 "5000" Keystone5000 1473,1103 r270 top
TP7 "5000" Keystone5000 1374,380 r0 top
TP8 "5000" Keystone5000 2130,977 r0 top
TP9 "5001" Keystone5001 2203.45,615 r0 top
TP10 "5000" Keystone5000 94,1317 r90 top
TP11 "5000" Keystone5000 1951,1595 r0 top
TP12 "5000" Keystone5000 1620,1595 r270 top
TP13 "5000" Keystone5000 242,1318 r90 top
TP14 "5000" Keystone5000 994,785 r0 top
TP15 "5000" Keystone5000 413.25,1693 r90 top
TP16 "5001" Keystone5001 873,1383 r90 top
TP17 "5000" Keystone5000 1116,609 r0 top
TP18 "5001" Keystone5001 3076,1076.19 r90 top locked
TP19 "5000" Keystone5000 379,641 r0 top
TP20 "5000" Keystone5000 383.54,798 r270 top
TP22 "5001" Keystone5001 535,336 r90 top
U1 "LM5050MK-1/NOPB" DDC0006A_N 1609,2466.94 r0 top
U2 "LM5069MM-2/NOPB" DGS0010A_N 2145,2405 r0 top
U3 "LM5164DDAT" DDA0008E_N 1969.62,784 r90 top locked
U4 "TPS26625DRCR" DRC0010J 552.64,1213 r180 top locked
U5 "TPS560430YDBVR" DBV0006A_N 1788.46,1342.62 r0 top locked
U6 "TPS2121RUXR" RUX0012A 1129.73,1113.57 r90 top locked
U7 "LP38691SD-3.3/NOPB" NGG0006A_V 1124,1464.91 r180 top locked
U8 "TPS22919DCKR" DCK0006A_N 692.33,652.58 r0 top locked
U9 "TPS3703A4330DSERQ1" DSE0006A 639.69,1579.15 r270 top locked
ZZ1 "This Assembly Note is for PCB labels only" AssemblyNoteLabel 1340.73,-1351 r0 top
ZZ2 "These assemblies are ESD sensitive, ESD precautions shall be observed." AssemblyNote 1340.73,-1448.22 r0 top
ZZ3 "These assemblies must be clean and free from flux and all contaminants. Use of no clean flux is not acceptable." AssemblyNote 1340.73,-1536.78 r0 top
ZZ4 "These assemblies must comply with workmanship standards IPC-A-610 Class 2, unless otherwise specified." AssemblyNote 1340.73,-1625.34 r0 top

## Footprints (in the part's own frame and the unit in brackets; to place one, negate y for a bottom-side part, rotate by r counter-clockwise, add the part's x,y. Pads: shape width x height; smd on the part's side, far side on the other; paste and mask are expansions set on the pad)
0603 [mm] "0603 from SM-752 data"
  rect 1x0.95 smd: 1(-0.8,0) 2(0.8,0)
  silkscreen extent -1.52,-0.69 1.52,0.69, body extent -0.87,-0.47 0.87,0.47, height 1
0603_HV [mil] "Ernesto recommended land pattern.  26 mil between pads."
  rect 30x30 smd: 1(-28,0) 2(28,0)
  silkscreen extent -52,-24 52,24, body extent -34,-19 34,19, height 39
0805_HV [mil] "0805 with 30mil clearance between pads"
  rect 50x63 smd: 1(-40,0) 2(40,0)
  silkscreen extent -74,-40 74,40, body extent -43,-29 43,29, height 57
1206 [mm] "1206 from SM-752 data"
  rect 1.3x1.85 smd: 1(-1.45,0) 2(1.45,0)
  silkscreen extent -2.4,-1.21 2.4,1.21, body extent -1.7,-0.9 1.7,0.9, height 1.35
1210_250 [mm] "1210"
  rect 1.3x2.7 smd: 1(-1.45,0) 2(1.45,0)
  silkscreen extent -2.32,-1.57 2.32,1.57, body extent -1.7,-1.35 1.7,1.35, height 2.5
1210_280 [mm] "SMD, 2-Leads, Body 3.6x2.8mm, Height 2.8mm"
  rect 1.1x2.2 smd: 1(-1.65,0) 2(1.65,0)
  silkscreen extent -0.84,-1.4 0.84,1.4, body extent -1.8,-1.4 1.8,1.4, height 2.8
5106 [mm] "Keystone"
  rect 0.99x1.4 smd: 1(-0.85,0) 2(0.88,0)
  silkscreen extent -1.63,-0.97 1.65,0.97, body extent -1.06,-0.69 1.06,0.69, height 0.84
Aavid_7109DG [mm] "Surface mount heat sink for D2PAK"
  rect 5x5 smd: 1(0,0)
  Top Layer region: -8.38,-10.16 -8.38,10.16 8.38,10.16 8.38,-10.16 5.335,-10.16 5.335,-7.62 -5.335,-7.62 -5.335,-10.16
  silkscreen extent -12.7,-9.69 12.7,9.69, body extent -12.7,-9.69 12.7,9.69, height 12.03
AssemblyNote [mil] "Assembly Note"
AssemblyNoteLabel [mil] "Assembly Note for PCB Labels"
CONN_PEC03SAAN [mm] "SULLINS"
  rect 1.5x1.5 hole 1.016: 1(-2.54,0)
  round 1.5 hole 1.016: 2(0,0) 3(2.54,0)
  silkscreen extent -4.72,-1.27 3.81,1.27, body extent -3.84,-1.3 3.84,1.3, height 8.38
DBV0006A_N [mm] "SOT23, 6-Leads, Body 2.9x1.6mm, Pitch 0.95mm, Lead Span 2.8mm, IPC Medium Density"
  rrect17% 1x0.6 smd: 1(-1.375,0.95) 2(-1.375,0) 3(-1.375,-0.95) 4(1.375,-0.95) 5(1.375,0) 6(1.375,0.95)
  silkscreen extent -1.68,-1.55 0.5,1.55, body extent -1.42,-1.46 1.42,1.46, height 1.12
DCK0006A_N [mm] "SOT23, 6-Leads, Body 2x1.3mm, Pitch 0.65mm, Lead Span 2.1mm, IPC Medium Density"
  rrect25% 0.85x0.4 smd: 1(-1.125,0.65) 2(-1.125,0) 3(-1.125,-0.65) 4(1.125,-0.65) 5(1.125,0) 6(1.125,0.65)
  silkscreen extent -1.5,-1.09 0.51,1.09, body extent -1.14,-1 1.14,1, height 0.95
DDA0008E_N [mm]
  rrect17% 1.45x0.6 smd: 1(-2.725,1.905) 2(-2.725,0.635) 3(-2.725,-0.635) 4(-2.725,-1.905) 5(2.725,-1.905) 6(2.725,-0.635) 7(2.725,0.635) 8(2.725,1.905)
  rrect7% 2.95x4.9 smd paste-1.5 mask-1.5: 9(0,0)
  rrect4% 2.4x3.1 on Top Paste: 9(0,0)
  rrect4% 2.4x3.1 on Top Solder: 9(0,0)
  silkscreen extent -3.22,-2.5 1.4,2.5, body extent -3,-2.45 3,2.45, height 1.57
DDC0006A_N [mm]
  rrect17% 1x0.6 smd: 1(-1.375,0.95) 2(-1.375,0) 3(-1.375,-0.95) 4(1.375,-0.95) 5(1.375,0) 6(1.375,0.95)
  silkscreen extent -1.75,-1.52 0.7,1.53, body extent -1.43,-1.48 1.43,1.49, height 0.92
DGS0010A_N [mm] "TSSOP, 10-Leads, Body 3x3mm, Pitch 0.5mm, IPC Medium Density"
  oval 1.35x0.3 smd: 1(-2.225,1) 2(-2.225,0.5) 3(-2.225,0) 4(-2.225,-0.5) 5(-2.225,-1) 6(2.225,-1) 7(2.225,-0.5) 8(2.225,0) 9(2.225,0.5) 10(2.225,1)
  silkscreen extent -2.75,-1.55 0.9,1.55, body extent -2.45,-1.5 2.45,1.5, height 0.96
DPAK [mm] "D-PAK, 3-Pads, Body 6.22x6.73mm (max), TO-252AA using nominal STEP model"
  rrect6% 2.6x1.6 smd: 1(-3.4,2.28) 3(-3.4,-2.28)
  rrect2% 6.2x5.8 smd paste-3: 2(3.4,0)
  body extent -3.86,-3.29 5.84,3.29, height 2.48
DRC0010J [mm] "VSON-10"
  rrect42% 0.6x0.24 smd: 1(-1.4,1) 2(-1.4,0.5) 3(-1.4,0) 4(-1.4,-0.5) 5(-1.4,-1) 6(1.4,-1) 7(1.4,-0.5) 8(1.4,0) 9(1.4,0.5) 10(1.4,1)
  rrect12% 1.65x2.4 smd paste-1 mask-2: 11(0,0)
  Top Layer region: -0.375,-1.65 -0.375,-1.2 -0.775,-1.2 -0.794,-1.196 -0.81,-1.185 -0.821,-1.169 -0.825,-1.15 -0.825,-1.15 -0.825,1.15 -0.821,1.169 -0.81,1.185 -0.794,1.196 -0.775,1.2 -0.775,1.2 -0.375,1.2 -0.375,1.65 -0.371,1.669 -0.36,1.685 -0.344,1.696 -0.325,1.7 -0.325,1.7 -0.325,1.7 -0.175,1.7 -0.175,1.7 -0.156,1.696 -0.14,1.685 -0.129,1.669 -0.125,1.65 -0.125,1.65 -0.125,1.2 0.125,1.2 0.125,1.65 0.129,1.669 0.14,1.685 0.156,1.696 0.175,1.7 0.175,1.7 0.175,1.7 0.325,1.7 0.325,1.7 0.344,1.696 0.36,1.685 0.371,1.669 0.375,1.65 0.375,1.65 0.375,1.2 0.775,1.2 0.794,1.196 0.81,1.185 0.821,1.169 0.825,1.15 0.825,1.15 0.825,-1.15 0.821,-1.169 0.81,-1.185 0.794,-1.196 0.775,-1.2 0.775,-1.2 0.375,-1.2 0.375,-1.65 0.371,-1.669 0.36,-1.685 0.344,-1.696 0.325,-1.7 0.325,-1.7 0.175,-1.7 0.156,-1.696 0.14,-1.685 0.129,-1.669 0.125,-1.65 0.125,-1.65 0.125,-1.2 -0.125,-1.2 -0.125,-1.65 -0.129,-1.669 -0.14,-1.685 -0.156,-1.696 -0.175,-1.7 -0.175,-1.7 -0.325,-1.7 -0.344,-1.696 -0.36,-1.685 -0.371,-1.669 -0.375,-1.65
  body extent -1.5,-1.5 1.5,1.5, height 1
DSE0006A [mm] "TI recommended land pattern"
  rect 0.66x0.25 smd: 1(-0.62,0.5)
  rect 0.7x0.25 smd: 2(-0.6,0) 3(-0.6,-0.5) 4(0.6,-0.5) 5(0.6,0) 6(0.6,0.5)
  Top Layer region: -0.3,0.625 -0.25,0.625 -0.15,0.525 -0.15,0.375 -0.3,0.375
  silkscreen extent -0.9,-0.92 0.9,0.92, body extent -0.77,-0.77 0.77,0.77, height 0.8
EB_H16 [mm] "SMD, 2-Leads, Dia 12.5mm, Pitch 9.7mm"
  rect 5.7x2 smd: 1(-4.85,0) 2(4.85,0)
  silkscreen extent -6.85,-6.85 6.85,6.85, body extent -6.85,-6.85 6.85,6.85, height 17.1
FCC_disclaimer [mil]
Fiducial10-20 [mm]
  round 1 smd mask+0.5: 1(0,0)
  Top Layer keep-out circle w1.178: c0,0 r0.5
IEC_HotSurface_Small [mil]
  silkscreen extent -107,-93 107,92
Keystone5000 [mil] "For Keystone 500x miniature loop terminals"
  round 80 hole 40: 1(0,0)
  silkscreen extent -52,-52 52,52, body extent -49,-49 49,49, height 182
Keystone5001 [mil] "For Keystone 500x miniature loop terminals"
  round 80 hole 40: 1(0,0)
  silkscreen extent -52,-52 52,52, body extent -49,-49 49,49, height 182
Keystone_1902C [mil] "Hex Standoff, 4-40 threaded, nylon"
  round 1 on Mech4: 0(0,0)
  body extent -145,-126 146,126, height 501
KTT0002A [mm] "TO-263-2"
  rrect10% 3.82x1.05 smd: 1(-6.9,2.54) 3(-6.9,-2.54)
  rrect1% 7.48x8.55 smd paste-4.2: 2(3.4,0)
  body extent -8.03,-5.08 7.05,5.08, height 4.67
ME3220 [mm] "Coilcraft SMT Power Inductor ME3220 inductors"
  rect 1.52x3.05 smd: 1(-1.145,0) 2(1.145,0)
  silkscreen extent -2.38,-1.88 2.34,1.88, body extent -1.75,-1.41 1.75,1.4
MSS1210 [mm] "Coilcraft MSS1210 series"
  rect 3x5.5 smd: 1(-4.75,0) 2(4.75,0)
  silkscreen extent -6.3,-6.3 6.3,6.3, body extent -6.15,-6.15 6.15,6.15, height 10.2
NGG0006A_V [mm] "SON, 6-Leads, Body 3x3 mm, Pitch 0.95mm, Full Paste, NSC Recommended"
  rrect29% 0.6x0.35 smd paste-0.025 mask+0.051: 1(-1.4,0.95) 2(-1.4,0) 3(-1.4,-0.95) 4(1.4,-0.95) 5(1.4,0) 6(1.4,0.95)
  rrect6% 1.6x2.1 smd paste-0.8 mask+0.051: 7(0,0)
  silkscreen extent -2.52,-1.7 1.85,1.72, body extent -1.55,-1.55 1.55,1.55, height 0.8
"NY PMS 440 0025 PH" [mm] "4-40 nylon screw and mounting hole"
  round 8 hole 3.2: 1(0,0)
  body extent -3.3,-3.3 3.3,3.3, height 2.69
Pb-Free_Overlay_Small [mil]
  silkscreen extent -46,-46 46,46
RUX0012A [mm] "VQFN-HR-12"
  rrect25% 1.05x0.4 smd: 1(-0.675,0.325) 2(-0.675,-0.375) 7(0.675,-0.375) 8(0.675,0.325)
  rrect40% 0.2x0.6 smd: 3(-0.75,-1.15) 4(-0.25,-1.15) 5(0.25,-1.15) 6(0.75,-1.15) 9(0.75,1.15) 10(0.25,1.15) 11(-0.25,1.15) 12(-0.75,1.15)
  silkscreen extent -1.15,-1.4 1.15,1.35, body extent -1.05,-1.3 1.05,1.3, height 1
SM_RADIAL_D [mm] "6.3 x 5.8mm:  Panasonic D"
  rect 3.2x1.6 smd: 1(-2.5,0) 2(2.5,0)
  silkscreen extent -3.4,-3.4 3.4,3.4, body extent -3.4,-3.4 3.4,3.4, height 6.1
SMA [mm] "Molded Diode, 2-Leads, Body 4.3x2.6mm, IPC Medium Density, based on OnSemi component dimensions and land pattern"
  rect 2x2 smd: 1(-2,0) 2(2,0)
  silkscreen extent -3.66,-1.57 2.79,1.57, body extent -2.6,-1.3 2.6,1.3, height 2.42
SMC_Bi [mil] "SMC, no polarity mark"
  rect 110x150 smd: 1(-140.49,0) 2(140.49,0)
  body extent -156,-116 156,116, height 92
SOD-123 [mm] "On Semi recommended land pattern"
  rect 0.915x1.22 smd: 1(-1.637,0) 2(1.637,0)
  silkscreen extent -2.74,-1.17 2.03,1.17, body extent -1.93,-0.9 1.93,0.9, height 1.35
SOT-23 [mm] "SOT23, 3-Leads, Body 2.9x1.3mm, Pitch 0.95mm, Lead Span 2.5mm, IPC Medium Density"
  rrect50% 1x0.6 smd: 1(-1.2,0.95) 2(-1.2,-0.95) 3(1.2,0)
  silkscreen extent -1.62,-1.5 0.7,1.5, body extent -1.16,-1.45 1.21,1.45, height 1
TE-1986660-2 [mm] "Terminal Block, 2 Pos, 10.16mm, TH"
  rrect50% 2.4x2.4 hole 1.6: 1(-5.08,-5.08) 1(-5.08,5.08)
  round 2.4 hole 1.6: 2(5.08,-5.08) 2(5.08,5.08)
  body extent -10.16,-11.8 10.82,6.68, height 28.6
TEC_282834-2 [mm] "TEC"
  rect 1.6x1.6 hole 1.1: 1(-1.27,0)
  round 1.6 hole 1.1: 2(1.27,0)
  silkscreen extent -3.66,-3.4 2.9,3.4, body extent -2.77,-3.25 2.77,3.25, height 10.01
WEEE_Minimum [mil] "WEEElie bin"
  silkscreen extent -95,-172 99,104
WSL4026_310 [mm] "SMD, 4-Leads, Body 6.6x10.14mm"
  rect 2.44x5.6 smd: 1(-4.115,-0.9) 2(4.115,-0.9)
  rect 2.44x0.89 smd: 3(-4.115,3.235) 4(4.135,3.235)
  silkscreen extent -5.25,-3.5 5.1,3.5, body extent -5.15,-3.25 5.15,3.65, height 3.1
WURTH_614104150121 [mm] "USB2.0 A, TH"
  rect 1.6x1.6 hole 0.94: 1(3.5,0)
  round 1.6 hole 0.94: 2(1,0) 3(-1,0) 4(-3.5,0)
  oval 1.3x2.2 hole 0.6 slot 1.5 at 90 deg: 5(-6.4,-7.35) 6(6.4,-7.35)
  silkscreen extent -7.3,-9.9 7.3,0.72, body extent -7.3,-9.9 7.3,0.1, height 6.93
YJN0003A [mm] "SMT, 3-Leads, Body 0.69x0.6mm"
  rrect80% 0.35x0.25 smd paste-0.2 mask-0.05: 1(-0.175,0.175) 2(-0.175,-0.175)
  rrect50% 0.25x0.2 on Top Paste: 1(-0.175,0.2) 2(-0.175,-0.2)
  rrect80% 0.25x0.6 smd paste-0.05 mask-0.05: 3(0.225,0)
  body extent -0.34,-0.3 0.35,0.3, height 0.22

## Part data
C1 C2: library part CMP-0860221-1, "CAP, AL, 33 µF, 160 V, +/- 20%, SMD", Cap_Case=12.5x16.5mm, Manufacturer=Panasonic, Tolerance_%=20%, Value2=160V, ValueDisplayed=33µF
C3 C4 C14: library part CMP-0009152-2, "CAP, CERM, 2.2 uF, 100 V, +/- 10%, X7R, AEC-Q200 Grade 1,", Cap_Case=1210_250, Manufacturer=TDK, Supplier Part Number 1=445-5866-1-ND, TempCo=X7R, Tolerance_%=10%, Value1="0.00173 ohm", Value2=100V, ValueDisplayed=2.2uF
C5 C7 C12: library part CMP-0081011-1, "CAP, CERM, 0.1 µF, 100 V,+/- 10%, X7R, AEC-Q200 Grade 1, 0603", Cap_Case=0603, Manufacturer="Taiyo Yuden", Supplier Part Number 1=587-6009-1-ND, TempCo=X7R, Tolerance_%=10%, Value2=100V, ValueDisplayed=0.1µF
C6: library part CMP-0008741-2, "CAP, CERM, 0.012 uF, 50 V, +/- 10%, X7R, 1206", Cap_Case=1206, Manufacturer="Yageo America", Supplier Part Number 1=311-1198-1-ND, TempCo=X7R, Tolerance_%=10%, Value1=Unknown, Value2=50V, ValueDisplayed=0.012uF
C8: library part CMP-0008531-2, "CAP, CERM, 0.01 uF, 50 V, +/- 10%, X7R, 1206", Cap_Case=1206, Manufacturer=AVX, Supplier Part Number 1=478-1542-1-ND, TempCo=X7R, Tolerance_%=10%, Value1="0.119 ohm", Value2=50V, ValueDisplayed=0.01uF
C9 C10: library part CMP-0006898-4, "CAP, CERM, 2200 pF, 50 V, +/- 10%, X7R, 0603", Cap_Case=0603, Manufacturer=Kemet, Supplier Part Number 1=399-1085-1-ND, TempCo=X7R, Tolerance_%=10%, Value1=Unknown, Value2=50V, ValueDisplayed=2200pF
C11: library part CMP-0007793-2, "CAP, CERM, 47 pF, 50 V, +/- 5%, C0G/NP0, 0805", Cap_Case=0805, Manufacturer=Kemet, Supplier Part Number 1=399-1117-1-ND, TempCo=C0G/NP0, Tolerance_%=5%, Value1="0.115 ohm", Value2=50V, ValueDisplayed=47pF
C13: library part CMP-0010730-1, "CAP, AL, 47 uF, 35 V, +/- 20%, 0.36 ohm, AEC-Q200 Grade 2, SMD", Cap_Case=D, Manufacturer=Panasonic, Supplier Part Number 1=PCE3842CT-ND, Tolerance_%=20%, Value1="0.36 ohm", Value2=35V, ValueDisplayed=47uF
C15 C17 C19 C21 C25 C26 C27 C29 C30 C33 C34 C35 C36 C38 C40 C42: library part CMP-0006753-4, "CAP, CERM, 0.1 uF, 25 V, +/- 10%, X7R, 0603", Cap_Case=0603, Manufacturer=AVX, Supplier Part Number 1=478-3714-1-ND, TempCo=X7R, Tolerance_%=10%, Value1="0.05 ohm", Value2=25V, ValueDisplayed=0.1uF
C16 C31 C37 C39: library part CMP-0007898-1, "CAP, CERM, 1 uF, 16 V, +/- 10%, X8R, 0805", Cap_Case=0805, Manufacturer=TDK, Supplier Part Number 1=445-8829-1-ND, TempCo=X8R, Tolerance_%=10%, Value1=Unknown, Value2=16V, ValueDisplayed=1uF
C18: library part CMP-0008378-2, "CAP, CERM, 10 uF, 25 V, +/- 10%, X7R, 0805", Cap_Case=0805, Manufacturer=MuRata, Supplier Part Number 1=81-GRM21BZ71E106KE5L, TempCo=X7R, Tolerance_%=10%, Value1=Unknown, Value2=25V, ValueDisplayed=10uF
C20 C28: library part CMP-0007885-2, "CAP, CERM, 4.7 uF, 35 V, +/- 10%, X7R, 0805", Cap_Case=0805, Manufacturer=TDK, Supplier Part Number 1=445-7555-1-ND, TempCo=X7R, Tolerance_%=10%, Value1="0.002346 ohm", Value2=35V, ValueDisplayed=4.7uF
C22: library part CMP-0009102-1, "CAP, CERM, 15 uF, 16 V, +/- 20%, X5R, 1210", Cap_Case=1210_280, Manufacturer=TDK, Supplier Part Number 1=445-7732-1-ND, TempCo=X5R, Tolerance_%=20%, Value1="0.002949 ohm", Value2=16V, ValueDisplayed=15uF
C23: library part CMP-0006900-4, "CAP, CERM, 0.022 uF, 16 V, +/- 10%, X7R, 0603", Cap_Case=0603, Manufacturer=Kemet, Supplier Part Number 1=399-1093-1-ND, TempCo=X7R, Tolerance_%=10%, Value1=Unknown, Value2=16V, ValueDisplayed=0.022uF
C32: library part CMP-0007730-2, "CAP, CERM, 1 uF, 50 V, +/- 10%, X7R, 0805", Cap_Case=0805, Manufacturer=Kemet, Supplier Part Number 1=399-7409-1-ND, TempCo=X7R, Tolerance_%=10%, Value1=Unknown, Value2=50V, ValueDisplayed=1uF
C41: library part CMP-0007136-5, "CAP, CERM, 1 uF, 16 V, +/- 10%, X7R, AEC-Q200 Grade 1, 0603", Cap_Case=0603, Manufacturer=MuRata, Supplier Part Number 1=490-5241-6-ND, TempCo=X7R, Tolerance_%=10%, Value1=Unknown, Value2=16V, ValueDisplayed=1uF
C43: library part CMP-0006922-4, "CAP, CERM, 3300 pF, 50 V, +/- 10%, X7R, 0603", Cap_Case=0603, Manufacturer=Kemet, Supplier Part Number 1=399-1086-1-ND, TempCo=X7R, Tolerance_%=10%, Value1=Unknown, Value2=50V, ValueDisplayed=3300pF
D2: library part CMP-0028773-3, "Diode, Schottky, 100 V, 3.5 A, DPAK", Manufacturer=Vishay-Semiconductor, Value1=3.5A, Value2=0.96V
D3: library part CMP-0085455-1, Manufacturer=STMicroelectronics, PartNumber=SMCJ26CA-TR, Value1=42.1V
D4: library part CMP-0028354-2, "Diode, Schottky, 100 V, 1.5 A, SMA", Manufacturer="International Rectifier", Value1=1.5A, Value2=0.68V
D5: library part CMP-0029001-2, "Diode, Ultrafast, 100 V, 0.15 A, SOD-123", Manufacturer="Diodes Inc.", Value1=0.15A, Value2=1.25V
FID1 FID2 FID3 FID4 FID5 FID6: library part CMP-0077181-1, "Fiducial mark.  There is nothing to buy or mount.", Manufacturer=N/A
H1 H2 H3 H4: library part CMP-0003617-1, "Machine Screw, Round, #4-40 x 1/4, Nylon, Philips panhead", Manufacturer="B&F Fastener Supply", Supplier Part Number 1=H542-ND
H5 H6 H7 H8: library part CMP-0003610-1, "Standoff, Hex, 0.5\"L #4-40 Nylon", Manufacturer=Keystone, Supplier Part Number 1=36-1902C-ND
H13 H15: library part CMP-0004038-1, "Surface mount heat sink for D2PAK", Manufacturer=Aavid, Supplier Part Number 1=HS406-ND
J1 J4 J5 J6 J8: library part CMP-0054974-1, "Terminal Block, 2x1, 2.54mm, TH", Manufacturer="TE Connectivity", Supplier Part Number 1=A98333-ND
J2 J3: library part CMP-0085661-1, "Terminal Block, 2 Pos, 10.16mm, TH", Color=Green, Current_A=65A, Manufacturer="TE Connectivity", Voltage_V=300V
J7: library part CMP-0002338-1, "Header, 100mil, 3x1, Tin, TH", Color=Black, Current_A=3A, Manufacturer="Sullins Connector Solutions", Supplier Part Number 1=S1012E-03-ND, Voltage_V=1.8kV
J9: library part CMP-0054815-1, "Connector, Receptacle, USB Type A, R/A, Bottom Mount TH", Manufacturer="Wurth Elektronik"
L1: library part CMP-0061864-2, "Inductor, Shielded, Ferrite, 150 uH, 2.5 A, 0.176 ohm, SMD", Manufacturer=Coilcraft, Supplier Part Number 1=994-MSS1210-154KEB, Value1="0.176 ohm", Value2=2.5A, ValueDisplayed=150uH
L2: library part CMP-0060543-1, "Inductor, Drum Core, Ferrite, 6.8 uH, 1.1 A, 0.27 ohm, SMD", Manufacturer=Coilcraft, Value1="0.27 ohm", Value2=1.1A, ValueDisplayed=6.8uH
Logo1: library part CMP-0074837-1, "IEC 61010-1 Hot Surface Warning"
Logo2: library part CMP-0074839-1
Logo3: library part CMP-0074847-1, "FCC_disclaimer"
Logo4: library part CMP-0074769-1
Q1 Q2: library part CMP-0000966-3, "MOSFET, N-CH, 100 V, 200 A, KTT0002A (TO-263-2)", Alternate Manufacturer=None, Manufacturer="Texas Instruments", Supplier Part Number 1=296-41136-1-ND, Value2="118 nC"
